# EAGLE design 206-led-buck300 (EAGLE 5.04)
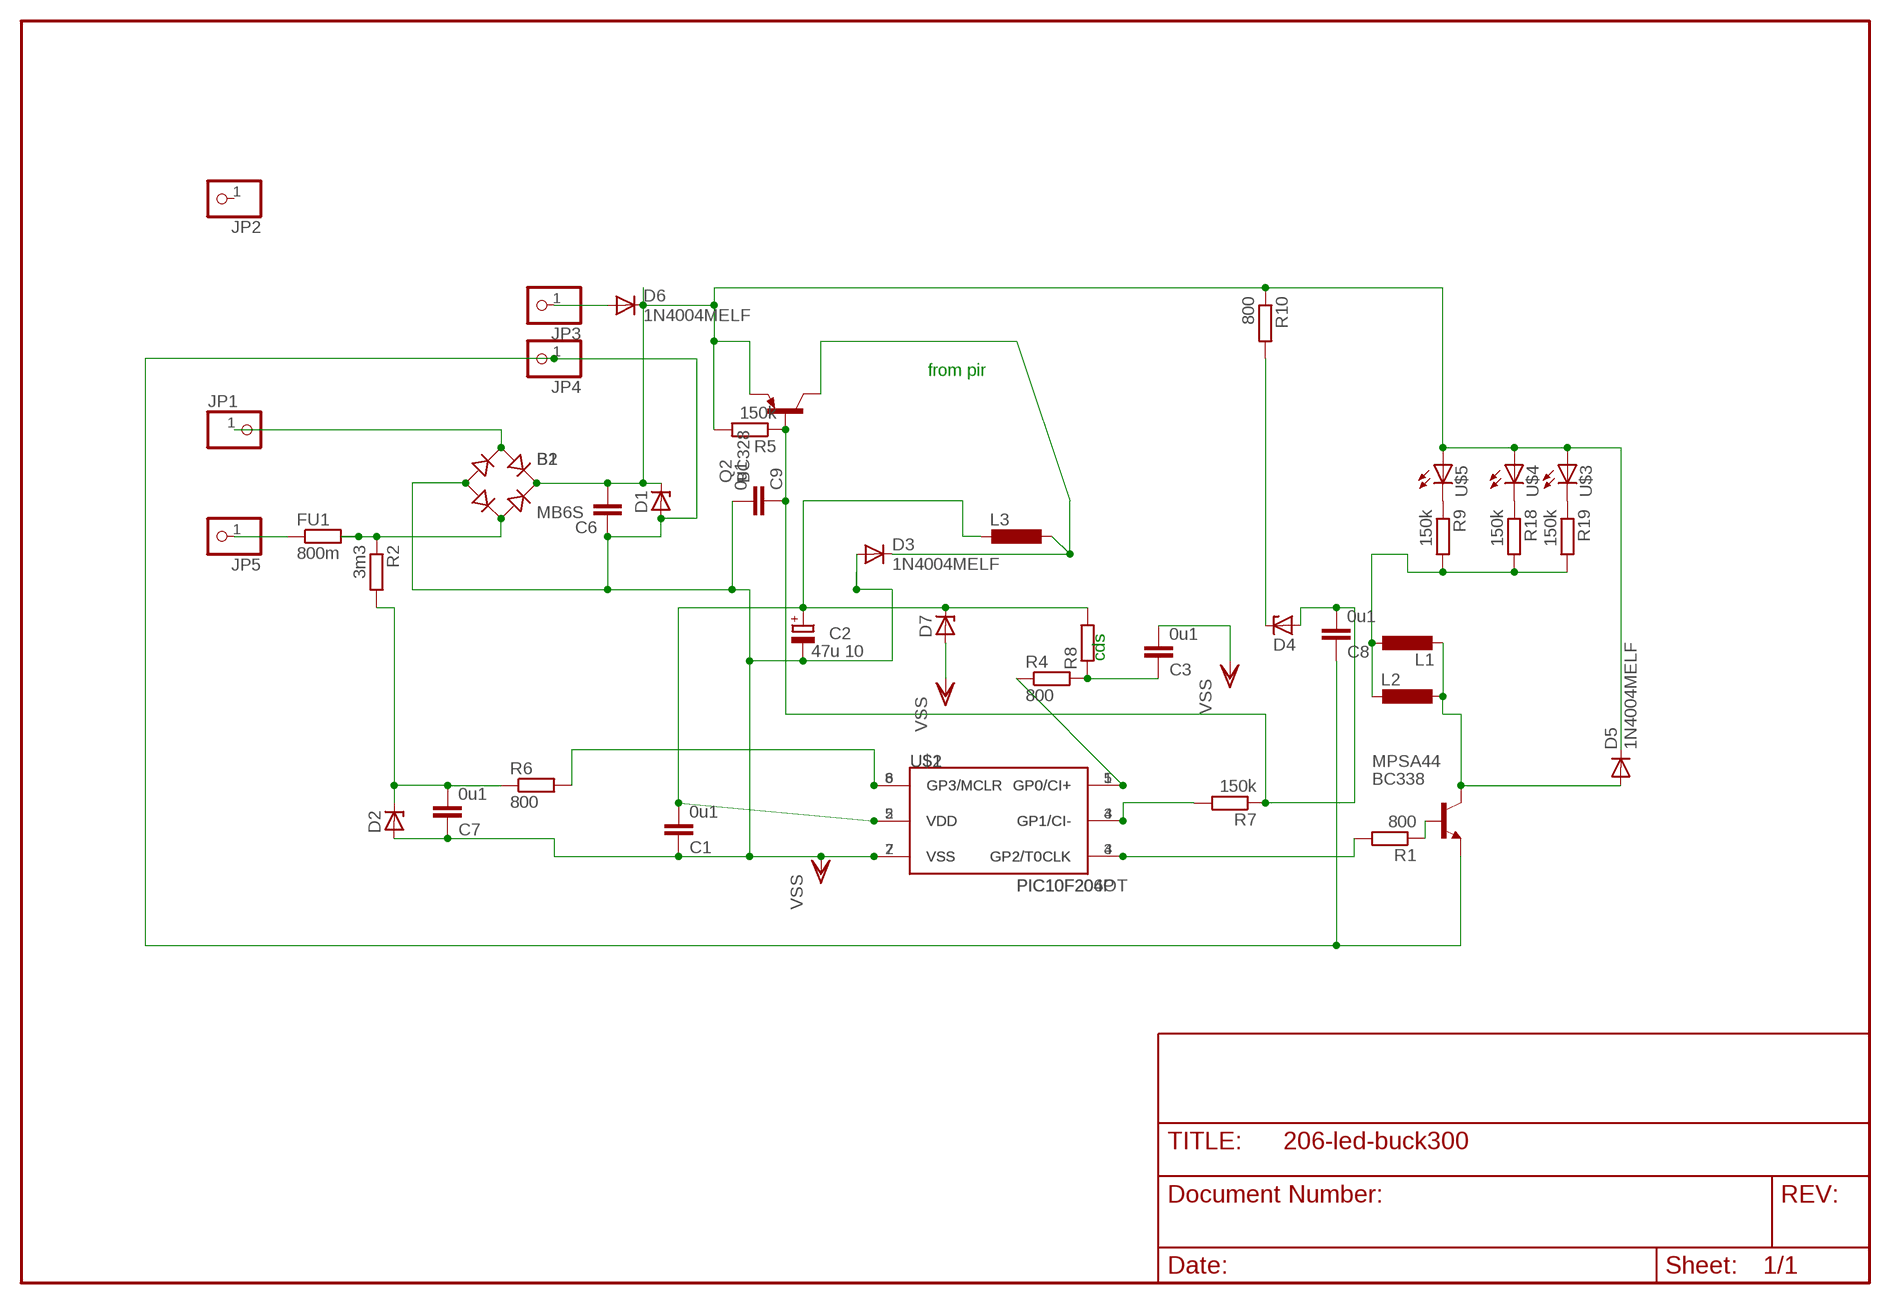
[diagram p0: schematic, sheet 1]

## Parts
B1  RB1A  [RB1A]
B2  MB6S  [SOIC-4]
C1  0u1  C-EUC1206  [C1206]
C2  47u 10  CPOL-EUE2.5-5  [E2,5-5]
C3  0u1  C-EUC1206  [C1206]
C6  C-EU050-025X075  [C050-025X075]
C7  0u1  C-EUC1206  [C1206]
C8  0u1  C-EUC1206  [C1206]
C9  0u1  C-EUC1206  [C1206]
D1  ZENER-DIODEZD-7.5  [ZDIO-7.5]
D2  ZENER-DIODESOT23  [SOT23]
D3  1N4004MELF  [MELF-MLL41]
D4  ZENER-DIODESOT23  [SOT23]
D5  1N4004MELF  [MELF-MLL41]
D6  1N4004MELF  [MELF-MLL41]
D7  ZENER-DIODEZD-7.5  [ZDIO-7.5]
FU1  800m  R-EU_0204/5  [0204/5]
JP1  PINHD-1X1  [1X01]
JP2  PINHD-1X1  [1X01]
JP3  PINHD-1X1  [1X01]
JP4  PINHD-1X1  [1X01]
JP5  PINHD-1X1  [1X01]
L1  L-EUL5650M  [L5650M]
L2  L-EU0207/7  [0207/7]
L3  L-EU0204V  [0204V]
MPSA44  BC338  [TO92-EBC]
Q2  BC328  [TO92-EBC]
R1  800  R-EU_R1206  [R1206]
R2  3m3  R-EU_R1206  [R1206]
R4  800  R-EU_R1206  [R1206]
R5  150k  R-EU_R1206  [R1206]
R6  800  R-EU_R1206  [R1206]
R7  150k  R-EU_R1206  [R1206]
R8  R-EU_0207/5V  [0207/5V]
R9  150k  R-EU_R1206  [R1206]
R10  800  R-EU_R1206  [R1206]
R18  150k  R-EU_R1206  [R1206]
R19  150k  R-EU_R1206  [R1206]
U$1  PIC10F206P  [DIL8]
U$2  PIC10F204OT  [SOT23-6]
U$3  LED5MM  [LED5MM]
U$4  LED5MM  [LED5MM]
U$5  LED5MM  [LED5MM]

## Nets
N$1: B1.+ B2.+ C6.2 D1.C D5.C D6.C Q2.E R5.2 R10.1 U$3.A U$4.A U$5.A
N$4: D6.A JP3.1
N$6: D4.3(C) R10.2
N$8: C8.2 C9.1 D4.1(A) Q2.B R5.1 R7.1
N$9: MPSA44.B R1.1
N$12: R6.2 U$1.8(GP3/MCLR) U$2.6(GP3/MCLR)
N$13: R7.2 U$1.4(GP1/CI-) U$2.3(GP1/CI-)
N$14: R1.2 U$1.3(GP2/T0CLK) U$2.4(GP2/T0CLK)
N$15: D3.C L3.1 Q2.C
N$16: C7.2 D2.3(C) R2.2 R6.1
N$17: FU1.1 JP5.1
N$18: B1.AC2 B2.~2(AC2) FU1.2 R2.1
N$20: B1.AC1 B2.~1(AC1) JP1.1
N$22: L1.1 L2.2 R9.2 R18.2 R19.2
N$23: C3.1 R4.2 R8.1
N$26: D5.A L1.2 L2.1 MPSA44.C
N$29: R4.1 U$1.5(GP0/CI+) U$2.1(GP0/CI+)
N$38: R9.1 U$5.K(C)
N$54: R18.1 U$4.K(C)
N$55: R19.1 U$3.K(C)
V2CC: C1.2 C2.+ D7.C L3.2 R8.2 U$1.2(VDD) U$2.5(VDD)
VSS: B1.- B2.- C1.1 C2.- C3.2 C6.1 C7.1 C8.1 C9.2 D1.A D2.1(A) D3.A D7.A JP4.1 MPSA44.E U$1.7(VSS) U$2.2(VSS)
Unconnected: JP2.1

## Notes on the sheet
- from pir
- cds

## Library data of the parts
B1 = rectifier:RB1A: RECTIFIER 1 A
B2 = rectifier:MB*S: Bridge Rectifier Source: http://www.fairchildsemi.com/ds/MB/MB6S.pdf
C1 C3 C6-C9 = rcl:C-EU: CAPACITOR, European symbol
C2 = rcl:CPOL-EU: POLARIZED CAPACITOR, European symbol
D1 D2 D4 D7 = diode-1:ZENER-DIODE: Z-Diode
D3 D5 D6 = diode-1:1N4004: DIODE
FU1 R1 R2 R4-R7 R9 R10 R18 R19 = rcl:R-EU_: RESISTOR, European symbol
JP1-JP5 = pinhead:PINHD-1X1: PIN HEADER
L1 = rcl-2:L-EU: INDUCTOR, European symbol
L2 L3 = rcl:L-EU: INDUCTOR, European symbol
MPSA44 = transistor-npn:BC338*: NPN Transistor
Q2 = transistor-pnp:BC328*: PNP Transistror
R8 = rcl(2):R-EU_: RESISTOR, European symbol
U$1 U$2 = microchip-3:PIC10F2*: uPC nW 0,25/0,5k Program Flash memory Comparator
U$3-U$5 = led(3):LED: LED

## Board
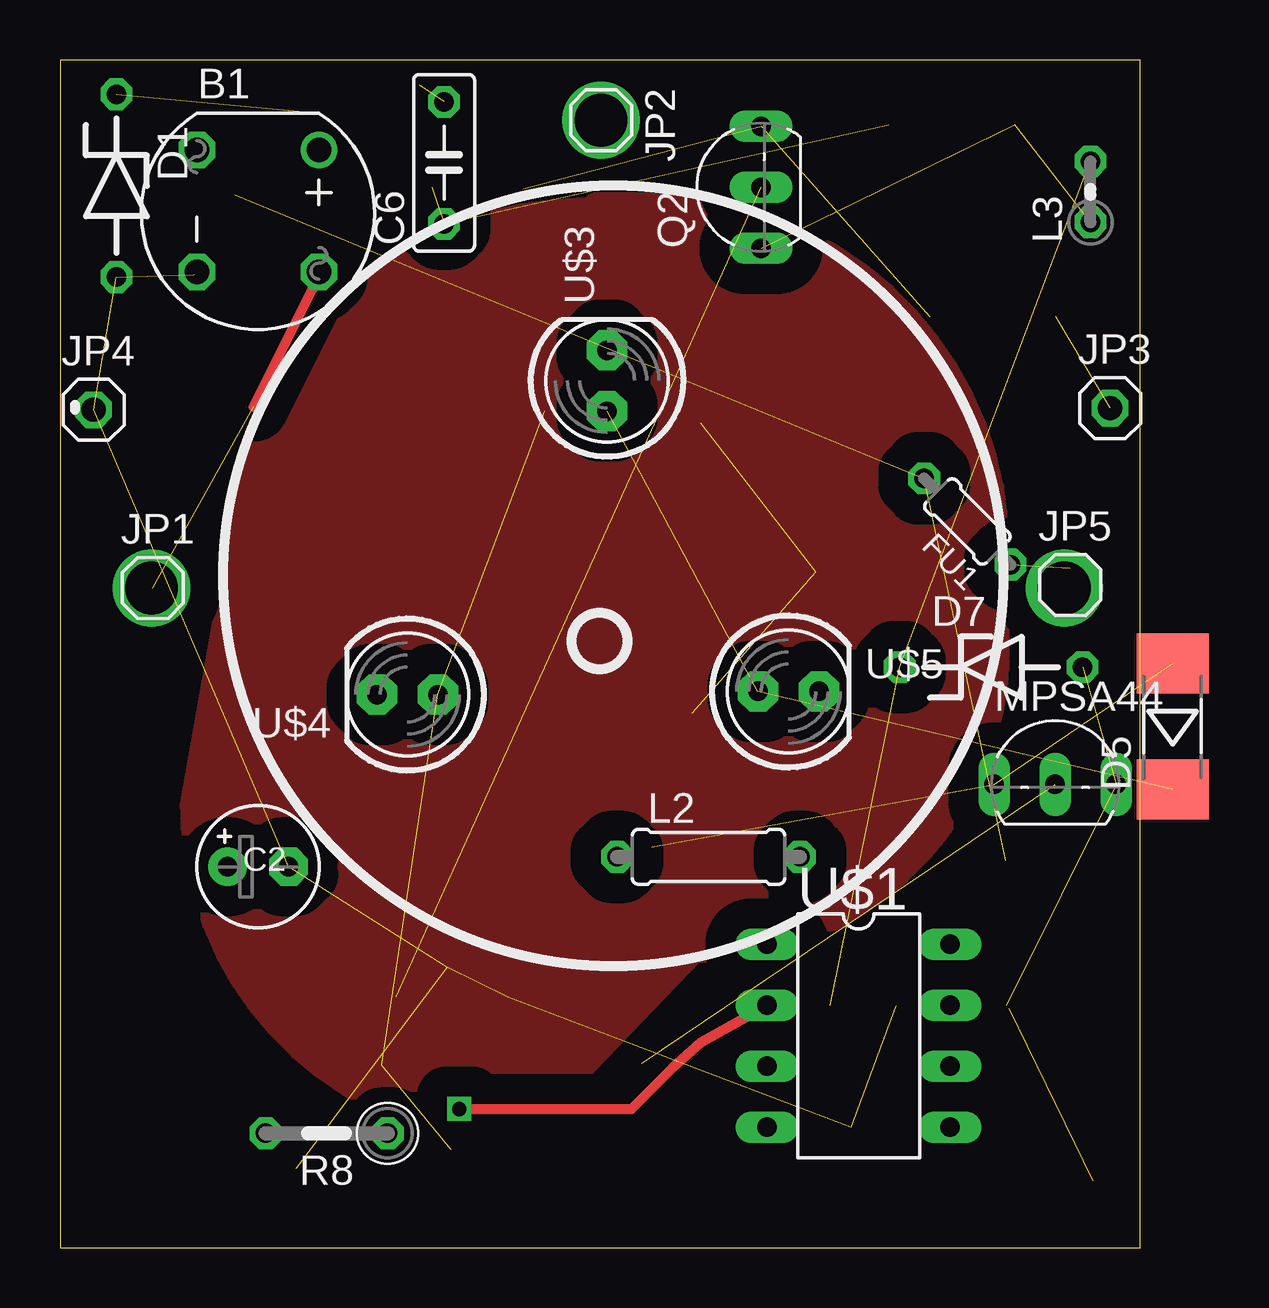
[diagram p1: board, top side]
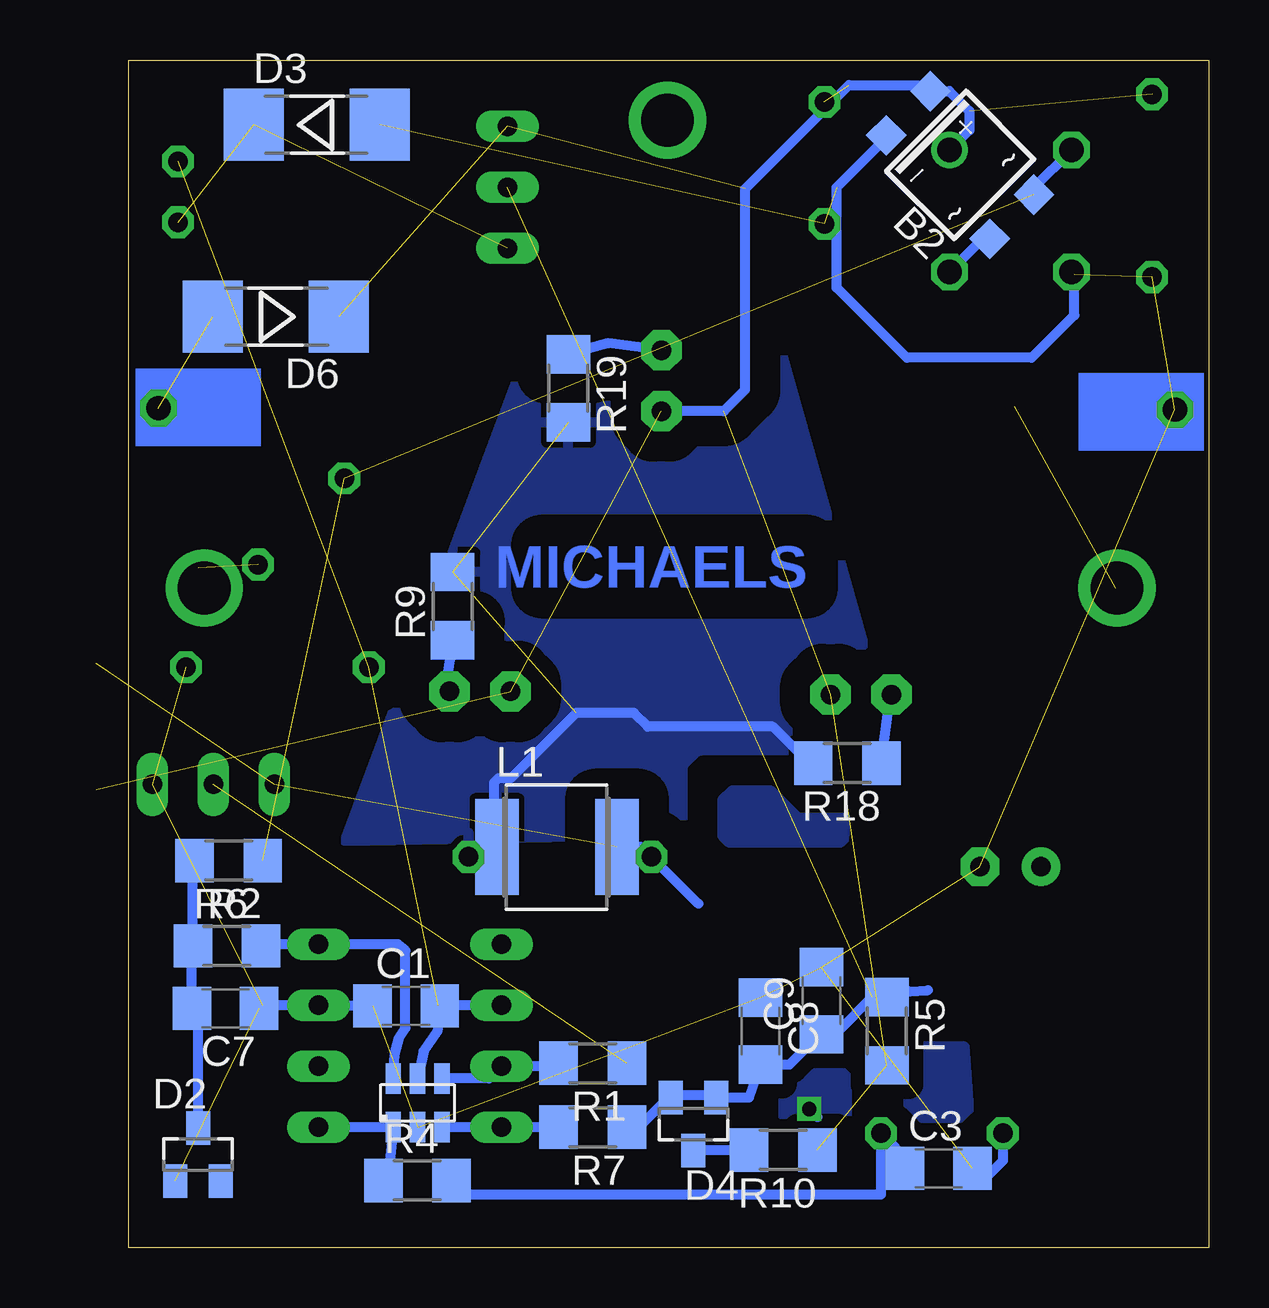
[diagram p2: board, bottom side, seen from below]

Size 45 x 49.5 mm. Coordinates in mm from the lower left corner, seen from the top.
Outline: 0,0 45,0 45,49.5 0,49.5 0,0
Copper layers (1*16): Top 0.035mm / dielectric 1.5mm / Bottom 0.035mm
Design rules "default": minimum track width 10mil, minimum drill 24mil, track to track 8mil, track to pad 8mil, pad to pad 8mil, via to via 8mil, smd to smd 8mil, copper to edge 40mil, drill to drill 8mil, minimum pad ring 10mil, minimum via ring 8mil, stop-mask expansion 4mil, vias tented up to drill 0mil, thermal gap 10mil

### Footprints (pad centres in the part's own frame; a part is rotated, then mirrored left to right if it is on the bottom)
RB1A = drill 1.016 round: + -2.54,2.54 | drill 1.016 octagon: - 2.54,-2.54; AC1 2.54,2.54; AC2 -2.54,-2.54
SOIC-4 = smd 1.2 x 1.2: + 1.3,3.05; - -1.3,3.05; ~1 -1.3,-3.05; ~2 1.3,-3.05
C1206 = smd 1.6 x 1.8: 1 -1.4,0; 2 1.4,0
E2,5-5 = drill 0.813 pad 1.6 round: + -1.27,0 | drill 0.813 pad 1.6 octagon: - 1.27,0
C050-025X075 = drill 0.813 octagon: 1 -2.54,0; 2 2.54,0
ZDIO-7.5 = drill 0.813 octagon: A 3.81,0; C -3.81,0
SOT23 = smd 1 x 1.4: 1 -0.95,-1.1; 2 0.95,-1.1; 3 0,1.1
MELF-MLL41 = smd 2.5 x 3: A 2.625,0; C -2.625,0
0204/5 = drill 0.813 octagon: 1 -2.54,0; 2 2.54,0
1X01 = drill 1.016 octagon: 1 0,0
L5650M = smd 1.8 x 4: 1 -2.5,0; 2 2.5,0
0207/7 = drill 0.813 octagon: 1 -3.81,0; 2 3.81,0
0204V = drill 0.813 octagon: 1 -1.27,0; 2 1.27,0
TO92-EBC = drill 0.813 long: B 0,-1.27; C -2.54,-1.27; E 2.54,-1.27
R1206 = smd 1.6 x 1.803: 1 -1.422,0; 2 1.422,0
0207/5V = drill 0.813 octagon: 1 -2.54,0; 2 2.54,0
DIL8 = drill 0.813 long: 1 -3.81,-3.81; 2 -1.27,-3.81; 3 1.27,-3.81; 4 3.81,-3.81; 5 3.81,3.81; 6 1.27,3.81; 7 -1.27,3.81; 8 -3.81,3.81
SOT23-6 = smd 0.635 x 1.27: 1 -1.016,-1.016; 2 0,-1.016; 3 1.016,-1.016; 4 1.016,1.016; 5 0,1.016; 6 -1.016,1.016
LED5MM = drill 0.813 pad 1.676 octagon: A -1.27,0; K 1.27,0

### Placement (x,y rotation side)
B1  8.25,43.21 270 top
B2  10.35,45.12 45 bottom
C1  33.43,10.08 0 bottom
C2  8.26,15.88 0 top
C3  11.24,3.3 0 bottom
C6  16,45.21 90 top
C7  40.96,9.97 180 bottom
C8  18.67,9.02 270 bottom
C9  16.13,10.29 90 bottom
D1  2.35,44.26 270 top
D2  42.1,3.87 0 bottom
D3  37.15,46.8 0 bottom
D4  21.46,5.14 180 bottom
D5  46.35,21.72 90 top
D6  38.86,38.8 180 bottom
D7  38.8,24.19 0 top
FU1  37.8,30.26 135 top
JP1  3.87,27.5 0 top
JP2  22.54,46.99 270 top
JP3  43.75,34.99 0 top
JP4  1.4,34.92 0 top
JP5  42.1,27.62 0 top
L1  27.15,16.69 0 bottom
L2  27.02,16.29 0 top
L3  42.94,44.01 90 top
MPSA44  41.47,20.57 0 top
Q2  27.94,44.2 90 top
R1  25.65,7.68 180 bottom
R2  40.83,16.13 180 bottom
R4  32.96,2.79 0 bottom
R5  13.4,9.02 270 bottom
R6  40.89,12.57 0 bottom
R7  25.65,5.02 180 bottom
R8  11.11,4.76 180 top
R9  31.5,26.73 90 bottom
R10  17.72,4.06 180 bottom
R18  15.05,20.19 180 bottom
R19  26.67,35.81 270 bottom
U$1  33.27,8.83 270 top
U$2  32.96,6.03 0 bottom
U$3  22.8,36.13 90 top
U$4  14.48,23.05 180 top
U$5  30.35,23.18 0 top

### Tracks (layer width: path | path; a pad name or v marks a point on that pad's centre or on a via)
N$1  (9 unrouted)
  Bottom 0.406: B1.+ 9.97,46.57 9.97,47.37 10.8,48.2 B2.+ 11.84,48.45 14.99,48.45 19.3,44.13 19.3,35.75 20.19,34.86 U$3.A
N$2  (via drill 2.2)
  other vias: 3.81,27.5
N$3  (via drill 2.2)
  other vias: 41.85,27.5
N$4  (1 unrouted)
N$5  (via drill 2.2)
  other vias: 22.54,46.99
N$6
  Bottom 0.406: D4.3 19.16,4.04 R10.2
N$7
  pour Top (isolate 1.27, rank 3): 21.97,43.56 arc90 6.99,28.57 5.21,18.48 arc90 19.24,4.45 26.54,12.06 arc90 39.37,24.89 39.37,29.02 arc90 24.64,43.75 22.23,43.75
  pour Bottom (isolate 0.61): 15.11,17.91 17.08,17.91 18.22,19.05 19.88,19.05 20.26,18.67 20.26,17.14 20,16.89 15.3,16.89 15.18,17.02
  pour Bottom (isolate 0.61): 10.16,8.38 12.13,8.38 13.02,7.49 13.02,6.48 11.94,5.4 10.35,5.4 9.97,5.78
N$8  (1 unrouted)
  Bottom 0.406: R7.1 23.75,5.02 22.42,6.35 20.75,6.35 D4.1 19.15,6.24 C8.2 17.46,7.62 16.7,8.38 C9.1 15.68,8.95 15.49,8.95 14.01,10.44 R5.1 13.25,10.67 12.45,10.67 11.68,10.73
N$9  (1 unrouted)
N$12
  Bottom 0.406: U$2.6 33.91,8.06 33.72,8.76 33.47,9.14 33.47,12.38 33.78,12.64 U$1.8 39.41,12.64 R6.2
N$13
  Bottom 0.406: R7.2 U$1.4 U$2.3
N$14
  Bottom 0.406: U$2.4 29.97,7.05 U$1.3 27.2,7.56 R1.2
N$15  (2 unrouted)
N$16
  Bottom 0.406: D2.3 42.1,9.71 C7.2 42.36,12.53 R6.1 42.32,16.07 R2.2
N$17  (1 unrouted)
  Bottom 0.406: JP5.1 42.1,28.32
N$18  (2 unrouted)
  Bottom 0.406: B2.~2 7.28,44.18 B1.AC2
N$20  (1 unrouted)
  Top 0.406: 8.06,35.05 10.54,39.96 B1.AC1
  Bottom 0.406: B2.~1 9.41,42.05 B1.AC1
N$22  (2 unrouted)
  Bottom 0.406: L2.2 30.42,16.69 L1.1 29.78,16.83 29.78,19.37 29.59,19.56 29.08,19.56 26.35,22.29 23.94,22.29 23.37,21.72 18.16,21.72 16.64,20.19 R18.2
  pour Bottom (isolate 1.27, rank 2): 21.97,38.29 28.07,38.23 36,16.95 12.19,17.4 17.97,37.97 21.59,38.23
N$23
  Bottom 0.406: C3.1 13.02,4.13 R8.1 13.65,2.2 31.09,2.2 R4.2
N$26  (2 unrouted)
  Bottom 0.406: 21.26,14.33 L2.1 23.62,16.69 L1.2
N$29
  Bottom 0.406: U$1.5 U$2.1 34.16,3.2 R4.1
N$38
  Bottom 0.406: U$5.K 31.81,23.18 R9.1
N$54
  Bottom 0.406: R18.1 13.27,22.99 U$4.K
N$55
  Bottom 0.406: U$3.K 25.02,37.69 R19.1
V2CC  (via drill 0.6)  (2 unrouted)
  Top 0.406: v16.64,5.78 23.81,5.78 25.53,7.49 26.73,8.57 U$1.2
  Bottom 0.406: U$2.5 32.7,8.19 32.13,9.02 32.07,9.47 C1.2 32.1,10.1 U$1.2 | 9.27,2.92 8.57,3.62 R8.2 | v16.64,5.78 16.29,5.44
  pour Bottom (isolate 0.61): 15.75,4.95 15.62,4.95 15.05,5.52 15.05,7.11 15.43,7.49 17.21,7.49 17.72,6.99 17.72,5.33 17.34,4.95
VSS  (13 unrouted)
  Bottom 0.406: C7.1 39.43,10.1 U$1.7 37.06,10.07 C1.1 | B2.- 13.43,46.26 15.49,44.2 15.49,40.01 12.57,37.08 7.37,37.08 5.59,38.86 5.59,40.55 B1.-
(copper drawn outside any net)
  shapes: Bottom area x2

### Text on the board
Bottom: MICHAELS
